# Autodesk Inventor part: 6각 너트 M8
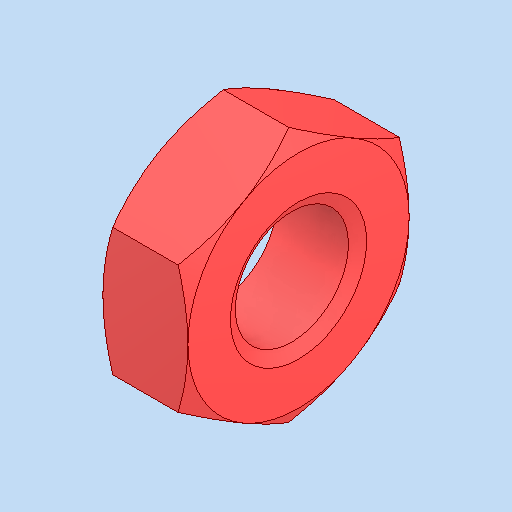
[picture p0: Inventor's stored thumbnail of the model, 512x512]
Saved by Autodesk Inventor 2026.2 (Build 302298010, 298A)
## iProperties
Created: 2026-08
Part Number: 6각 너트 M8
Material: 강철, 연강
Description: 6각 너트
Document SubType Name: Modeling
Designer: PC2-02
Density: 7.85 g/cm^3
Appearance: 기본값
Author: jhkim
Sending System: Autodesk Inventor 2027
Preprocessor: ST-DEVELOPER v20.1
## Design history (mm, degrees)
feature "Solid1"
node "솔리드1"
